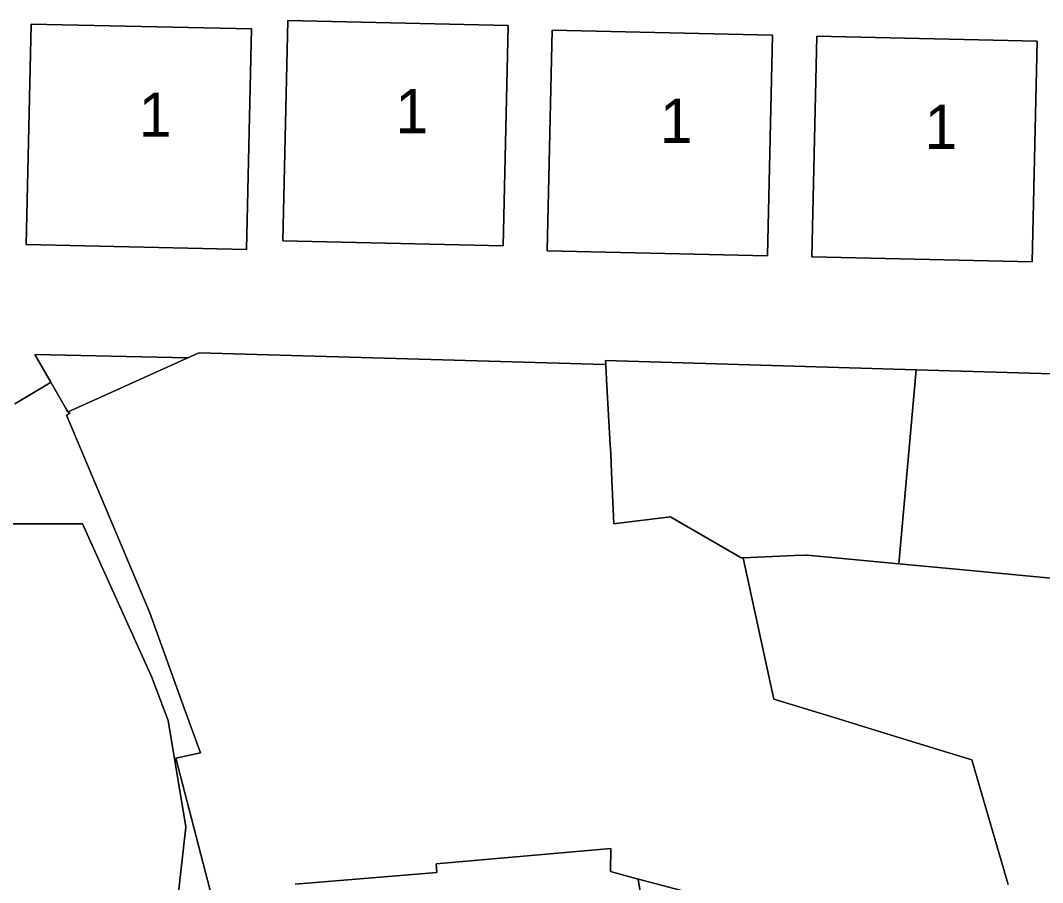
# Model space of a CAD drawing. Extents: x 598968 to 613553, y 4409678 to 4430833.
# Drawn here: x 608130.3 to 608408.5, y 4415273.1 to 4415507.6 of the extents above; entities that cross this region are included whole.
import ezdxf

# ---------------------------------------------------------------- set-up
doc = ezdxf.new("R2010")
doc.units = 0
for name, color, linetype in [('1', 7, 'Continuous'), ('Sòl Rústic Comú', 7, 'Continuous'), ('ZONA 1. Illes regulars - ANNEX III B', 7, 'Continuous')]:
    doc.layers.add(name, color=color, linetype=linetype)

msp = doc.modelspace()

# ---------------------------------------------------------------- linework, layer by layer
at = {"layer": '1'}
for points in [[(608193.1262, 4415505.2888), (608191.7713, 4415445.3048), (608131.7873, 4415446.6588), (608133.1422, 4415506.6428)], [(608263.0118, 4415506.2532), (608261.6569, 4415446.2692), (608201.673, 4415447.6232), (608203.0279, 4415507.6072)], [(608334.9655, 4415503.6109), (608333.6106, 4415443.6269), (608273.6266, 4415444.9809), (608274.9815, 4415504.9649)], [(608407.0011, 4415501.9766), (608405.6462, 4415441.9926), (608345.6622, 4415443.3466), (608347.0171, 4415503.3306)], [(608175.8118, 4415415.8301), (608134.211, 4415416.7621), (608138.4965, 4415409.2648), (608142.4879, 4415402.2821), (608143.1322, 4415401.1549), (608143.2314, 4415401.1995)], [(608374.0993, 4415412.6064), (608289.5173, 4415415.1128), (608289.5784, 4415414.0243), (608289.601, 4415413.622), (608289.9025, 4415408.2564), (608290.8069, 4415392.1627), (608290.9108, 4415389.7778), (608291.132, 4415384.6975), (608291.7413, 4415370.7046), (608292.347, 4415370.7778), (608292.4199, 4415370.7866), (608307.2176, 4415372.5749), (608307.4249, 4415372.4549), (608317.9639, 4415366.3509), (608324.9112, 4415362.3271), (608326.4547, 4415361.4331), (608327.0031, 4415361.4574), (608340.9182, 4415362.0744), (608343.9952, 4415362.2108), (608344.3893, 4415362.1739), (608369.3619, 4415359.8267)]]:
    msp.add_lwpolyline(points, close=True, dxfattribs=at)
for points in [[(608128.7456, 4415403.3263), (608137.7552, 4415408.678), (608138.4965, 4415409.2648), (608134.211, 4415416.7621), (608175.8118, 4415415.8301), (608178.8126, 4415417.1776), (608289.3328, 4415414.0391), (608289.5784, 4415414.0243), (608289.5173, 4415415.1128), (608374.0993, 4415412.6064), (608435.9019, 4415410.7678)], [(608399.0981, 4415272.5738), (608393.5475, 4415291.5706), (608389.1959, 4415306.4828), (608380.8829, 4415309.0038), (608367.2803, 4415313.2252), (608351.7233, 4415317.994), (608335.3525, 4415323.0102), (608332.5703, 4415335.5054), (608327.0891, 4415361.003), (608327.0031, 4415361.4574), (608326.4547, 4415361.4331), (608324.9112, 4415362.3271), (608317.9639, 4415366.3509), (608307.4249, 4415372.4549), (608307.2176, 4415372.5749), (608292.4199, 4415370.7866), (608292.347, 4415370.7778), (608291.7413, 4415370.7046), (608291.132, 4415384.6975), (608290.9108, 4415389.7778), (608290.8069, 4415392.1627), (608289.9025, 4415408.2564), (608289.601, 4415413.622), (608289.5784, 4415414.0243), (608289.3328, 4415414.0391), (608178.8126, 4415417.1776), (608175.8118, 4415415.8301), (608143.2314, 4415401.1995), (608143.6017, 4415400.6602), (608143.8319, 4415400.7636), (608142.8425, 4415400.2036), (608165.5031, 4415346.4872), (608174.4983, 4415321.5902), (608179.2825, 4415308.3902), (608172.5861, 4415306.924), (608183.5825, 4415264.3702)], [(608435.9019, 4415410.7678), (608374.0993, 4415412.6064), (608369.3619, 4415359.8267), (608386.9044, 4415358.1778), (608394.4298, 4415357.4507), (608418.3183, 4415355.1455)], [(608205.0301, 4415272.6814), (608243.5725, 4415275.8202), (608243.3703, 4415278.2), (608290.9125, 4415282.3802), (608290.8725, 4415276.1002), (608298.4111, 4415274.0796), (608298.4415, 4415274.0714), (608311.1825, 4415270.6564)]]:
    msp.add_lwpolyline(points, dxfattribs=at)
at = {"layer": 'Sòl Rústic Comú'}
for points in [[(608183.5825, 4415264.3702), (608172.5861, 4415306.924), (608179.2825, 4415308.3902), (608174.4983, 4415321.5902), (608165.5031, 4415346.4872), (608142.8425, 4415400.2036), (608143.8319, 4415400.7636), (608143.6017, 4415400.6602), (608143.2314, 4415401.1995), (608143.1322, 4415401.1549), (608142.4879, 4415402.2821), (608138.4965, 4415409.2648), (608137.7552, 4415408.678), (608128.7456, 4415403.3263)], [(608041.8905, 4415151.858), (608051.3817, 4415313.1964), (608113.2577, 4415370.6966), (608147.1329, 4415370.6966), (608165.9455, 4415329.1966), (608170.5081, 4415317.1966), (608175.3081, 4415288.2708), (608175.3205, 4415288.1966), (608167.8201, 4415222.1966)], [(608167.8201, 4415222.1966), (608175.3205, 4415288.1966), (608175.3081, 4415288.2708), (608170.5081, 4415317.1966), (608165.9455, 4415329.1966), (608147.1329, 4415370.6966), (608113.2577, 4415370.6966), (608051.3817, 4415313.1964), (608041.8905, 4415151.858)], [(608418.3183, 4415355.1455), (608394.4298, 4415357.4507), (608386.9044, 4415358.1778), (608369.3619, 4415359.8267), (608344.3893, 4415362.1739), (608343.9952, 4415362.2108), (608340.9182, 4415362.0744), (608327.0031, 4415361.4574), (608327.0891, 4415361.003), (608332.5703, 4415335.5054), (608335.3525, 4415323.0102), (608351.7233, 4415317.994), (608367.2803, 4415313.2252), (608380.8829, 4415309.0038), (608389.1959, 4415306.4828), (608393.5475, 4415291.5706), (608399.0981, 4415272.5738)], [(608301.2591, 4415256.1968), (608298.4111, 4415274.0796), (608290.8725, 4415276.1002), (608290.9125, 4415282.3802), (608243.3703, 4415278.2), (608243.5725, 4415275.8202), (608205.0301, 4415272.6814)], [(608311.1825, 4415270.6564), (608298.4415, 4415274.0714), (608298.4111, 4415274.0796), (608301.2591, 4415256.1968)]]:
    msp.add_lwpolyline(points, dxfattribs=at)
at = {"layer": 'ZONA 1. Illes regulars - ANNEX III B'}
for points in [[(608193.1262, 4415505.2888), (608133.1422, 4415506.6428), (608131.7873, 4415446.6588), (608191.7713, 4415445.3048)], [(608263.0118, 4415506.2532), (608203.0279, 4415507.6072), (608201.673, 4415447.6232), (608261.6569, 4415446.2692)], [(608334.9655, 4415503.6109), (608274.9815, 4415504.9649), (608273.6266, 4415444.9809), (608333.6106, 4415443.6269)], [(608407.0011, 4415501.9766), (608347.0171, 4415503.3306), (608345.6622, 4415443.3466), (608405.6462, 4415441.9926)]]:
    msp.add_lwpolyline(points, close=True, dxfattribs=at)

# ---------------------------------------------------------------- texts
for p in [(608162.4567, 4415475.9738), (608232.3424, 4415476.9382), (608304.2961, 4415474.2959), (608376.3317, 4415472.6616)]:
    msp.add_text('1', height=12, dxfattribs=at).set_placement(p)

doc.saveas('drawing.dxf')
